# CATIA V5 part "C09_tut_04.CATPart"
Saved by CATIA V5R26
Part number: Part1
Bounding box of the stored display mesh (mm): x -112.5 to 112.5, y -202.31 to 80, z -202.31 to 85
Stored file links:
  D:\_Deepak\CATIA\CATIA V5 2015 Parts Files\Tutorial Files\Tutorials\c09_catia_v5_6r2015_tut\C09_tut_04.CATPart
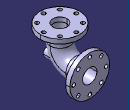
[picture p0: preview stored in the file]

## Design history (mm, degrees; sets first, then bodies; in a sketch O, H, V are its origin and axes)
Body1 (main body)
  Sketch1 on yz-plane, origin (0, 0, 0), H (0, 1, 0), V (0, 0, 1)
    line L1 (-90, 60) -> (-90, 0)
    point P1 (-90, 60)
    arc A1 centre (0, 0) radius 90 from (-90, 0) to (0, -90) ccw
    point P3 (0, 0)
    line L2 (0, -90) -> (55, -90)
    point P5 (55, -90)
    distance P1 L2 = 150
    distance P5 L1 = 145
    radius A1 = 90
    vertical: L1 V
    tangency: A1 L1, L2 A1
    horizontal: L2 H
    coincidence: P3 O
  Plane1: type Normal, Curve Sketch1, RefPoint Sketch1.P5, Ratio 0
  Sketch2 on Plane1, origin (0, 55, 0), H (-1, 0, 0), V (0, 0, 1)
    circle A1 centre (0, -90) radius 48.5
    point P1 (0, -90)
    reference projected point E1 (0, -90) from Sketch1.P5
    radius A1 = 48.5
    coincidence: P1 V, P1 E1
  Rib1: profile Sketch2, centre curve Sketch1, thin wall 16
  Sketch3 on face of Rib1, origin (0, 55, 0), H (-1, 0, 0), V (0, 0, 1)
    circle A1 centre (0, -90) radius 112.5
    point P1 (0, -90)
    reference projected circle E1 centre (0, -90) radius 56.5 from edge [face of Rib1 | face of Rib1]
    circle A2 centre (0, -90) radius 40.5
    reference projected circle E2 centre (0, -90) radius 40.5 from edge [face of Rib1 | face of Rib1]
    radius A1 = 112.5
    coincidence: P1 V, A2 E2
    concentricity: A1 E1
  Pad1: profile Sketch3, direction (0, 1, 0), length 25
  Sketch4 on face of Rib1, origin (0, 0, 60), H (1, 0, 0), V (0, 1, 0)
    circle A1 centre (0, -90) radius 112.5
    point P1 (0, -90)
    reference projected circle E1 centre (0, -90) radius 56.5 from edge [face of Rib1 | face of Rib1]
    circle A2 centre (0, -90) radius 40.5
    reference projected circle E2 centre (0, -90) radius 40.5 from edge [face of Rib1 | face of Rib1]
    radius A1 = 112.5
    coincidence: P1 V, A2 E2
    concentricity: A1 E1
  Pad2: profile Sketch4, direction (0, 0, 1), length 25
  Plane2: type Offset, RefPlane end face of Pad1, Offset 240
  Sketch5 on Plane2, origin (0, -160, 0), H (-1, 0, 0), V (0, 0, 1)
    circle A1 centre (0, -90) radius 25
    point P1 (0, -90)
    reference projected line E1 (-112.5, 85) -> (112.5, 85) from edge [face of Pad2 from Sketch4.A1 | end face of Pad2]
    radius A1 = 25
    distance E1 P1 = 175
    coincidence: P1 V
  Pad3: profile Sketch5, direction (0, 1, 0), up to the existing solid (limit type 2)
  Point1: type Center, Curve edge [start face of Pad3 | face of Pad3 from Sketch5.A1]
  Sketch6 on start face of Pad3, origin (0, -160, -90), H (1, 0, 0), V (0, 0, 1)
    point P1 (0, 0)
    reference projected point E1 (0, 0) from Point1
    coincidence: E1 P1
  Hole1: placed by Sketch6, at (0, -160, -90) direction (0, 1, 0), diameter 20, through (limit type 6), counterbore diameter 24, counterbore depth 28
  Sketch7 on end face of Pad1, origin (0, 80, 0), H (-1, 0, 0), V (0, 0, 1)
    construction circle A1 centre (0, -90) radius 92.5
    point P1 (0, -90)
    reference projected circle E1 centre (0, -90) radius 112.5 from edge [face of Pad1 from Sketch3.A1 | end face of Pad1]
    point P2 (0, 2.5)
    radius A1 = 92.5
    coincidence: P1 V, P2 A1, P2 V
    concentricity: A1 E1
  Sketch8 on end face of Pad1, origin (0, 80, 2.5), H (1, 0, 0), V (0, 0, -1)
    point P1 (0, 0)
    reference projected point E1 (0, 0) from Sketch7.P2
    coincidence: E1 P1
  Hole2: placed by Sketch8, at (0, 80, 2.5) direction (0, -1, 0), diameter 20.5, through (limit type 6)
  CircPattern1: of Hole2, instances 8, angular step 45 {= 360.0*1 deg/CircPattern1.AngularNumber}, axis from face of Pad1
  Sketch9 on end face of Pad2, origin (0, 0, 85), H (1, 0, 0), V (0, 1, 0)
    construction circle A1 centre (0, -90) radius 92.5
    point P1 (0, -90)
    reference projected circle E1 centre (0, -90) radius 112.5 from edge [face of Pad2 from Sketch4.A1 | end face of Pad2]
    point P2 (0, 2.5)
    radius A1 = 92.5
    coincidence: P1 V, P2 A1, P2 V
    concentricity: A1 E1
  Sketch10 on end face of Pad2, origin (0, 2.5, 85), H (1, 0, 0), V (0, 1, 0)
    point P1 (0, 0)
    reference projected point E1 (0, 0) from Sketch9.P2
    coincidence: E1 P1
  Hole3: placed by Sketch10, at (0, 2.5, 85) direction (0, 0, -1), diameter 20.5, through (limit type 6)
  CircPattern2: of Hole3, instances 8, angular step 45 {= 360.0*1 deg/CircPattern2.AngularNumber}, axis from face of Pad2 from Sketch4.A2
